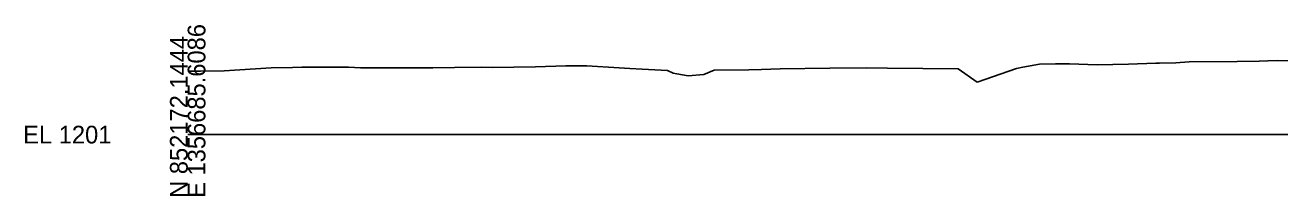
# Model space of a CAD drawing. Extents: x -26 to 4603, y -10 to 4066.
# Drawn here: x -25.7 to 172.6, y 1990.3 to 2017.3 of the extents above; entities that cross this region are included whole.
import ezdxf

# ---------------------------------------------------------------- set-up
doc = ezdxf.new("R2010")
doc.units = 0
doc.layers.add('Exist Cross Section Cell', color=7, linetype='Continuous')
doc.layers.add('Exist XS Ground Line', color=7, linetype='Continuous')

msp = doc.modelspace()

# ---------------------------------------------------------------- linework, layer by layer
at = {"layer": 'Exist Cross Section Cell'}
msp.add_line((0, 2000), (200, 2000), dxfattribs=at)
at = {"layer": 'Exist XS Ground Line'}
for p, q in [((54.98, 2010.72), (59.78, 2010.89)), ((59.78, 2010.89), (60.69, 2010.9)), ((60.69, 2010.9), (63.1, 2010.89)), ((63.1, 2010.89), (68.21, 2010.56)), ((131.96, 2010.66), (134.62, 2011.14)), ((134.62, 2011.14), (137.13, 2011.17)), ((137.13, 2011.17), (139.34, 2011.21)), ((139.34, 2011.21), (143.73, 2011.02)), ((143.73, 2011.02), (148.69, 2011.14)), ((148.69, 2011.14), (152.99, 2011.29)), ((152.99, 2011.29), (153.6, 2011.31)), ((153.6, 2011.31), (156.18, 2011.36)), ((156.18, 2011.36), (158.29, 2011.5)), ((158.29, 2011.5), (165.86, 2011.58)), ((165.86, 2011.58), (169.31, 2011.62)), ((169.31, 2011.62), (170.7, 2011.68)), ((170.7, 2011.68), (172.29, 2011.71)), ((172.29, 2011.71), (178.41, 2011.64)), ((0, 2010.04), (1.68, 2010.03)), ((1.68, 2010.03), (2.04, 2010.04)), ((2.04, 2010.04), (5.78, 2010.09)), ((5.78, 2010.09), (13.19, 2010.55)), ((13.19, 2010.55), (16.54, 2010.62)), ((16.54, 2010.62), (18.02, 2010.67)), ((18.02, 2010.67), (20.32, 2010.69)), ((20.32, 2010.69), (21.08, 2010.68)), ((21.08, 2010.68), (25.4, 2010.65)), ((25.4, 2010.65), (27.3, 2010.58)), ((27.3, 2010.58), (31.54, 2010.54)), ((31.54, 2010.54), (38.72, 2010.58)), ((38.72, 2010.58), (42.16, 2010.6)), ((42.16, 2010.6), (46.45, 2010.65)), ((46.45, 2010.65), (48.12, 2010.61)), ((48.12, 2010.61), (54.98, 2010.72)), ((68.21, 2010.56), (69.85, 2010.47)), ((69.85, 2010.47), (71.83, 2010.36)), ((71.83, 2010.36), (75.8, 2010.14)), ((75.8, 2010.14), (76.7, 2009.74)), ((76.7, 2009.74), (77.29, 2009.61)), ((77.29, 2009.61), (79.08, 2009.28)), ((79.08, 2009.28), (81.58, 2009.51)), ((81.58, 2009.51), (83.21, 2010.17)), ((83.21, 2010.17), (88.69, 2010.24)), ((88.69, 2010.24), (90.67, 2010.28)), ((90.67, 2010.28), (93.65, 2010.41)), ((93.65, 2010.41), (101.48, 2010.51)), ((101.48, 2010.51), (107.33, 2010.58)), ((107.33, 2010.58), (110.58, 2010.49)), ((110.58, 2010.49), (121.77, 2010.42)), ((121.77, 2010.42), (124.78, 2008.27)), ((124.78, 2008.27), (130.99, 2010.47)), ((130.99, 2010.47), (131.96, 2010.66))]:
    msp.add_line(p, q, dxfattribs=at)

# ---------------------------------------------------------------- texts
at = {"layer": 'Exist Cross Section Cell'}
for s, p in [('E 1356685.6086', (2.8, 1990)), ('N 852172.1444', (0, 1990))]:
    msp.add_text(s, height=2.8, rotation=90, dxfattribs=at).set_placement(p)
msp.add_text('EL 1201', height=2.8, dxfattribs=at).set_placement((-26, 1998.6))

doc.saveas('drawing.dxf')
